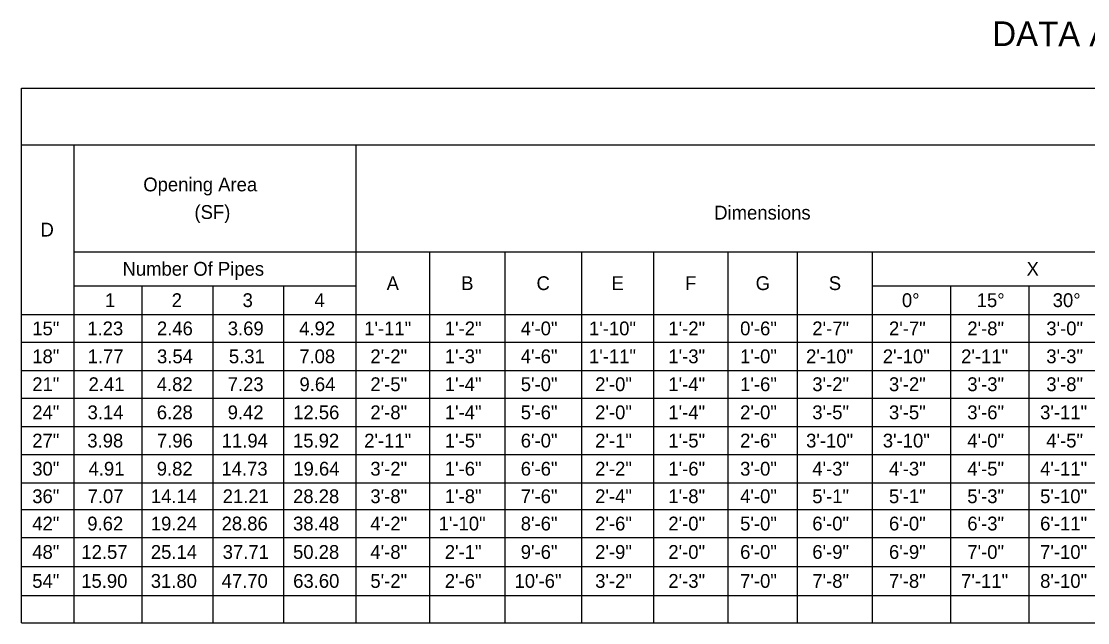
# Model space of a CAD drawing. Extents: x 10029 to 10796, y 10063 to 10519.
# Drawn here: x 10029 to 10299.4, y 10366.5 to 10518.9 of the extents above; entities that cross this region are included whole.
import ezdxf

# ---------------------------------------------------------------- set-up
doc = ezdxf.new("R2010")
doc.units = 0
doc.layers.add('Default', color=7, linetype='Continuous')
doc.layers.add('Dimension', color=7, linetype='Continuous')

msp = doc.modelspace()

# ---------------------------------------------------------------- linework, layer by layer
at = {"layer": 'Default'}
for p, q in [((10028.97, 10502.01), (10795.89, 10502.01)), ((10028.97, 10366.47), (10028.97, 10502.01)), ((10028.97, 10487.65), (10795.89, 10487.65)), ((10042.36, 10366.47), (10042.36, 10487.65)), ((10113.89, 10366.47), (10113.89, 10487.65)), ((10042.36, 10460.49), (10783.03, 10460.49)), ((10132.57, 10366.47), (10132.57, 10460.49)), ((10151.63, 10366.47), (10151.63, 10460.49)), ((10171.07, 10366.47), (10171.07, 10460.49)), ((10189.38, 10366.47), (10189.38, 10460.49)), ((10208.18, 10366.47), (10208.18, 10460.49)), ((10225.79, 10366.47), (10225.79, 10460.49)), ((10244.78, 10366.47), (10244.78, 10460.49)), ((10042.36, 10451.88), (10113.89, 10451.88)), ((10059.62, 10366.47), (10059.62, 10451.88)), ((10077.6, 10366.47), (10077.6, 10451.88)), ((10095.57, 10366.47), (10095.57, 10451.88)), ((10244.78, 10451.88), (10783.03, 10451.88)), ((10264.68, 10366.47), (10264.68, 10451.88)), ((10284.51, 10366.47), (10284.51, 10451.88)), ((10028.97, 10444.58), (10795.89, 10444.58)), ((10028.97, 10437.55), (10795.89, 10437.55)), ((10028.97, 10430.43), (10795.89, 10430.43)), ((10028.97, 10423.41), (10795.89, 10423.41)), ((10028.97, 10416.18), (10795.89, 10416.18)), ((10028.97, 10409.08), (10795.89, 10409.08)), ((10028.97, 10401.92), (10795.89, 10401.92)), ((10028.97, 10395.12), (10795.89, 10395.12)), ((10028.97, 10388.08), (10795.89, 10388.08)), ((10028.97, 10380.7), (10795.89, 10380.7)), ((10028.97, 10373.4), (10795.89, 10373.4)), ((10028.97, 10366.47), (10795.89, 10366.47))]:
    msp.add_line(p, q, dxfattribs=at)

# ---------------------------------------------------------------- texts
at = {"layer": 'Dimension'}
for s, height, rotation, p in [('DATA AND ESTIMATED QUANTITIES FOR ONE ENDWALL', 6.25, 359.7555, (10275.18, 10512.68)), ('15"', 3.5, 0, (10031.74, 10439.32)), ('1.23', 3.5, 0, (10045.69, 10439.32)), ('2.46', 3.5, 0, (10063.35, 10439.32)), ('3.69', 3.5, 0, (10081.32, 10439.32)), ('4.92', 3.5, 0, (10099.43, 10439.32)), ('1\'-11"', 3.5, 0, (10115.91, 10439.32)), ('1\'-2"', 3.5, 0, (10136.35, 10439.32)), ('4\'-0"', 3.5, 0, (10155.61, 10439.32)), ('1\'-10"', 3.5, 0, (10172.91, 10439.32)), ('1\'-2"', 3.5, 0, (10193.04, 10439.32)), ('0\'-6"', 3.5, 0, (10211.24, 10439.32)), ('2\'-7"', 3.5, 0, (10229.54, 10439.32)), ('2\'-7"', 3.5, 0, (10248.99, 10439.32)), ('2\'-8"', 3.5, 0, (10268.85, 10439.32)), ('3\'-0"', 3.5, 0, (10288.88, 10439.32)), ('18"', 3.5, 0, (10031.74, 10432.24)), ('1.77', 3.5, 0, (10045.77, 10432.24)), ('3.54', 3.5, 0, (10063.38, 10432.24)), ('5.31', 3.5, 0, (10081.6, 10432.24)), ('7.08', 3.5, 0, (10099.44, 10432.24)), ('2\'-2"', 3.5, 0, (10117.48, 10432.24)), ('1\'-3"', 3.5, 0, (10136.35, 10432.24)), ('4\'-6"', 3.5, 0, (10155.61, 10432.24)), ('1\'-11"', 3.5, 0, (10172.91, 10432.24)), ('1\'-3"', 3.5, 0, (10193.04, 10432.24)), ('1\'-0"', 3.5, 0, (10211.24, 10432.24)), ('2\'-10"', 3.5, 0, (10227.97, 10432.24)), ('2\'-10"', 3.5, 0, (10247.42, 10432.24)), ('2\'-11"', 3.5, 0, (10267.28, 10432.24)), ('3\'-3"', 3.5, 0, (10288.88, 10432.24)), ('21"', 3.5, 0, (10031.74, 10425.17)), ('2.41', 3.5, 0, (10046.01, 10425.17)), ('4.82', 3.5, 0, (10063.31, 10425.17)), ('7.23', 3.5, 0, (10081.29, 10425.17)), ('9.64', 3.5, 0, (10099.5, 10425.17)), ('2\'-5"', 3.5, 0, (10117.48, 10425.17)), ('1\'-4"', 3.5, 0, (10136.35, 10425.17)), ('5\'-0"', 3.5, 0, (10155.61, 10425.17)), ('2\'-0"', 3.5, 0, (10174.48, 10425.17)), ('1\'-4"', 3.5, 0, (10193.04, 10425.17)), ('1\'-6"', 3.5, 0, (10211.24, 10425.17)), ('3\'-2"', 3.5, 0, (10229.54, 10425.17)), ('3\'-2"', 3.5, 0, (10248.99, 10425.17)), ('3\'-3"', 3.5, 0, (10268.85, 10425.17)), ('3\'-8"', 3.5, 0, (10288.88, 10425.17)), ('24"', 3.5, 0, (10031.74, 10418.04)), ('3.14', 3.5, 0, (10045.76, 10418.04)), ('6.28', 3.5, 0, (10063.32, 10418.04)), ('9.42', 3.5, 0, (10081.29, 10418.04)), ('12.56', 3.5, 0, (10097.9, 10418.04)), ('2\'-8"', 3.5, 0, (10117.48, 10418.04)), ('1\'-4"', 3.5, 0, (10136.35, 10418.04)), ('5\'-6"', 3.5, 0, (10155.61, 10418.04)), ('2\'-0"', 3.5, 0, (10174.48, 10418.04)), ('1\'-4"', 3.5, 0, (10193.04, 10418.04)), ('2\'-0"', 3.5, 0, (10211.24, 10418.04)), ('3\'-5"', 3.5, 0, (10229.54, 10418.04)), ('3\'-5"', 3.5, 0, (10248.99, 10418.04)), ('3\'-6"', 3.5, 0, (10268.85, 10418.04)), ('3\'-11"', 3.5, 0, (10287.31, 10418.04)), ('27"', 3.5, 0, (10031.74, 10410.88)), ('3.98', 3.5, 0, (10045.7, 10410.88)), ('7.96', 3.5, 0, (10063.35, 10410.88)), ('11.94', 3.5, 0, (10079.79, 10410.88)), ('15.92', 3.5, 0, (10097.86, 10410.88)), ('2\'-11"', 3.5, 0, (10115.91, 10410.88)), ('1\'-5"', 3.5, 0, (10136.35, 10410.88)), ('6\'-0"', 3.5, 0, (10155.61, 10410.88)), ('2\'-1"', 3.5, 0, (10174.48, 10410.88)), ('1\'-5"', 3.5, 0, (10193.04, 10410.88)), ('2\'-6"', 3.5, 0, (10211.24, 10410.88)), ('3\'-10"', 3.5, 0, (10227.97, 10410.88)), ('3\'-10"', 3.5, 0, (10247.42, 10410.88)), ('4\'-0"', 3.5, 0, (10268.85, 10410.88)), ('4\'-5"', 3.5, 0, (10288.88, 10410.88)), ('30"', 3.5, 0, (10031.74, 10403.75)), ('4.91', 3.5, 0, (10046.01, 10403.75)), ('9.82', 3.5, 0, (10063.31, 10403.75)), ('14.73', 3.5, 0, (10079.71, 10403.75)), ('19.64', 3.5, 0, (10097.93, 10403.75)), ('3\'-2"', 3.5, 0, (10117.48, 10403.75)), ('1\'-6"', 3.5, 0, (10136.35, 10403.75)), ('6\'-6"', 3.5, 0, (10155.61, 10403.75)), ('2\'-2"', 3.5, 0, (10174.48, 10403.75)), ('1\'-6"', 3.5, 0, (10193.04, 10403.75)), ('3\'-0"', 3.5, 0, (10211.24, 10403.75)), ('4\'-3"', 3.5, 0, (10229.54, 10403.75)), ('4\'-3"', 3.5, 0, (10248.99, 10403.75)), ('4\'-5"', 3.5, 0, (10268.85, 10403.75)), ('4\'-11"', 3.5, 0, (10287.31, 10403.75)), ('36"', 3.5, 0, (10031.74, 10396.77)), ('7.07', 3.5, 0, (10045.77, 10396.77)), ('14.14', 3.5, 0, (10061.81, 10396.77)), ('21.21', 3.5, 0, (10080.03, 10396.77)), ('28.28', 3.5, 0, (10097.87, 10396.77)), ('3\'-8"', 3.5, 0, (10117.48, 10396.77)), ('1\'-8"', 3.5, 0, (10136.35, 10396.77)), ('7\'-6"', 3.5, 0, (10155.61, 10396.77)), ('2\'-4"', 3.5, 0, (10174.48, 10396.77)), ('1\'-8"', 3.5, 0, (10193.04, 10396.77)), ('4\'-0"', 3.5, 0, (10211.24, 10396.77)), ('5\'-1"', 3.5, 0, (10229.54, 10396.77)), ('5\'-1"', 3.5, 0, (10248.99, 10396.77)), ('5\'-3"', 3.5, 0, (10268.85, 10396.77)), ('5\'-10"', 3.5, 0, (10287.31, 10396.77)), ('42"', 3.5, 0, (10031.74, 10389.85)), ('9.62', 3.5, 0, (10045.69, 10389.85)), ('19.24', 3.5, 0, (10061.81, 10389.85)), ('28.86', 3.5, 0, (10079.75, 10389.85)), ('38.48', 3.5, 0, (10097.87, 10389.85)), ('4\'-2"', 3.5, 0, (10117.48, 10389.85)), ('1\'-10"', 3.5, 0, (10134.78, 10389.85)), ('8\'-6"', 3.5, 0, (10155.61, 10389.85)), ('2\'-6"', 3.5, 0, (10174.48, 10389.85)), ('2\'-0"', 3.5, 0, (10193.04, 10389.85)), ('5\'-0"', 3.5, 0, (10211.24, 10389.85)), ('6\'-0"', 3.5, 0, (10229.54, 10389.85)), ('6\'-0"', 3.5, 0, (10248.99, 10389.85)), ('6\'-3"', 3.5, 0, (10268.85, 10389.85)), ('6\'-11"', 3.5, 0, (10287.31, 10389.85)), ('48"', 3.5, 0, (10031.74, 10382.64)), ('12.57', 3.5, 0, (10044.2, 10382.64)), ('25.14', 3.5, 0, (10061.81, 10382.64)), ('37.71', 3.5, 0, (10080.03, 10382.64)), ('50.28', 3.5, 0, (10097.87, 10382.64)), ('4\'-8"', 3.5, 0, (10117.48, 10382.64)), ('2\'-1"', 3.5, 0, (10136.35, 10382.64)), ('9\'-6"', 3.5, 0, (10155.61, 10382.64)), ('2\'-9"', 3.5, 0, (10174.48, 10382.64)), ('2\'-0"', 3.5, 0, (10193.04, 10382.64)), ('6\'-0"', 3.5, 0, (10211.24, 10382.64)), ('6\'-9"', 3.5, 0, (10229.54, 10382.64)), ('6\'-9"', 3.5, 0, (10248.99, 10382.64)), ('7\'-0"', 3.5, 0, (10268.85, 10382.64)), ('7\'-10"', 3.5, 0, (10287.31, 10382.64)), ('54"', 3.5, 0, (10031.74, 10375.3)), ('15.90', 3.5, 0, (10044.16, 10375.3)), ('31.80', 3.5, 0, (10061.79, 10375.3)), ('47.70', 3.5, 0, (10079.76, 10375.3)), ('63.60', 3.5, 0, (10097.9, 10375.3)), ('5\'-2"', 3.5, 0, (10117.48, 10375.3)), ('2\'-6"', 3.5, 0, (10136.35, 10375.3)), ('10\'-6"', 3.5, 0, (10154.03, 10375.3)), ('3\'-2"', 3.5, 0, (10174.48, 10375.3)), ('2\'-3"', 3.5, 0, (10193.04, 10375.3)), ('7\'-0"', 3.5, 0, (10211.24, 10375.3)), ('7\'-8"', 3.5, 0, (10229.54, 10375.3)), ('7\'-8"', 3.5, 0, (10248.99, 10375.3)), ('7\'-11"', 3.5, 0, (10267.28, 10375.3)), ('8\'-10"', 3.5, 0, (10287.31, 10375.3))]:
    msp.add_text(s, height=height, rotation=rotation, dxfattribs=at).set_placement(p)
for s, p in [('Opening Area', (10059.89, 10475.82)), ('(SF)', (10072.87, 10468.82)), ('Dimensions', (10204.67, 10468.68)), ('D', (10033.83, 10464.37)), ('Number Of Pipes', (10054.63, 10454.43)), ('X', (10283.88, 10454.43)), ('A', (10121.6, 10450.79)), ('B', (10140.51, 10450.79)), ('C', (10159.61, 10450.79)), ('E', (10178.64, 10450.79)), ('F', (10197.29, 10450.79)), ('G', (10215.18, 10450.79)), ('S', (10233.72, 10450.79)), ('1', (10050.18, 10446.48)), ('2', (10067.1, 10446.48)), ('3', (10085.07, 10446.48)), ('4', (10103.3, 10446.48)), ('0°', (10252.27, 10446.48)), ('15°', (10271.24, 10446.48)), ('30°', (10290.51, 10446.48))]:
    msp.add_text(s, height=3.5, dxfattribs=at).set_placement(p)

doc.saveas('drawing.dxf')
